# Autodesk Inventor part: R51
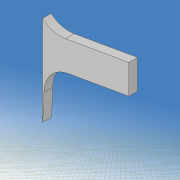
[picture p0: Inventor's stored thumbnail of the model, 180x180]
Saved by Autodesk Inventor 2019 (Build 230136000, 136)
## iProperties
Created: 2021-05
Part Number: R51
Material: 一般
Document SubType Name: Modeling
Designer: kikut
Density: 1 g/cm^3
Appearance: 既定
Mass: 0.00804985 g
Surface Area: 0.369476 cm^2
Volume: 0.00804985 cm^3
Author: kikut
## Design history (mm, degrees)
sketch "スケッチ1"
  geometry: L1 (80, 60)-(-80, 60); L2 (-80, 60)-(-80, -60); L3 (-80, -60)-(80, -60); L4 (80, -60)-(80, 60); L5 (80, 60)-(-80, -60); L6 (-80, 60)-(80, -60); 1 further point
  constraints: 12 end point, 2 midpoint, 2 parallel, 1 horizontal, 1 perpendicular
  dimensions: "d0" = 160 distance of L2.end L3.end; "d1" = 120 distance of L1.end L2.end
extrude "押し出し1" new body sketch "スケッチ1" stored distance "d2" = 0.6; taper "d3" = 0 deg
sketch "スケッチ2"
  geometry: L1 (-140, 0)-(140, 0) reference; L2 (0, -54)-(20, -30); L3 (0, 54)-(20, 30); L4 (0, -3)-(6.514, -3); L5 (6.514, -3)-(16, -6); L6 (16, -6)-(24, -3); L7 (24, -3)-(33.716, -3); L8 (0, 3)-(6.514, 3); L9 (6.514, 3)-(16, 6); L10 (16, 6)-(24, 3); L11 (24, 3)-(33.716, 3); L12 (0, -98)-(0, 98) reference; L13 (-100, -70)-(100, -70); L14 (100, -70)-(100, 70); L15 (100, 70)-(-100, 70); L16 (-100, 70)-(-100, -70); L17 (-100, -70)-(100, 70); L18 (100, -70)-(-100, 70); A1 r 60 centre (54.312, 28.5) between (0, 54) and (0, 3); A2 r 60 centre (54.312, -28.5) between (0, -3) and (0, -54); A3 r 18.111 centre (18, -12) between (20, -30) and (33.716, -3); A4 r 18.111 centre (18, 12) between (33.716, 3) and (20, 30); 1 further point
  constraints: 32 end point, 8 point on circle, 8 symmetric about line, 4 centre point, 3 horizontal, 2 collinear, 2 midpoint, 2 parallel, 1 perpendicular
  dimensions: "d5" = 60 radius of A1; "d6" = 6 distance of L8.start L4.start; "d7" = 108 distance of L3.start L2.start; "d8" = 0 horizontal distance of L3.start L8.start; "d9" = 60 distance of L3.end L2.end; "d10" = 0 horizontal distance of point (0, 0) L3.start; "d11" = 20 horizontal distance of L3.start L3.end; "d12" = 24 distance of A4.centre A3.centre; "d13" = 6 distance of L11.end L7.end; "d14" = 12 distance of L9.end L5.end; "d15" = 16 distance from line of L12 L5.end; "d16" = 24 distance from line of L6.end L12; "d17" = 200 distance of L14.end L15.end; "d18" = 140 distance of L15.end L13.start; "d30" = 18 distance from line of L12 A4.centre
extrude "押し出し2" cut sketch "スケッチ2" stored distance "d19" = 10; taper "d20" = 0 deg
sketch "スケッチ3"
  geometry: L1 (49.705, -17.97)-(33.948, -15.191); L2 (33.948, -15.191)-(34.295, -13.222); L3 (34.295, -13.222)-(50.052, -16); L4 (50.052, -16)-(49.705, -17.97); L5 (49.705, -17.97)-(34.295, -13.222); L6 (33.948, -15.191)-(50.052, -16); L7 (50.052, 16)-(34.295, 13.222); L8 (34.295, 13.222)-(33.948, 15.191); L9 (33.948, 15.191)-(49.705, 17.97); L10 (49.705, 17.97)-(50.052, 16); L11 (50.052, 16)-(33.948, 15.191); L12 (34.295, 13.222)-(49.705, 17.97); L13 (-112, 0)-(112, 0) reference; L14 (0, -84)-(0, 84) reference; 3 further points
  constraints: 24 end point, 4 midpoint, 4 parallel, 2 perpendicular, 2 symmetric about line
  dimensions: "d21" = 2 distance of L3.end L1.start; "d22" = 2 distance of L9.end L7.start; "d23" = 16 distance of L8.end L9.end; "d24" = 42 distance from line of L14 point (42, 15.596); "d26" = 10 deg angle of L7 L13; "d62" = 16 distance from line of L3.end L13
extrude "押し出し3" join sketch "スケッチ3" distance "d27" = 0.6; taper "d28" = 0 deg
fillet "フィレット1" dims "d31" = 2
fillet "フィレット2" dims "d32" = 1
sketch "スケッチ6"
  geometry: L1 (-20, 60)-(80, 60); L2 (80, 60)-(80, -60); L3 (80, -60)-(-20, -60); L4 (-20, -60)-(-20, 60); L5 (-46.168, 0)-(93.832, 0) reference; L6 (0, -84)-(0, 84) reference; L7 (36, 10)-(42, 10); L8 (42, 10)-(42, 20); L9 (42, 20)-(36, 20); L10 (36, 20)-(36, 10); 1 further point
  constraints: 16 end point, 4 parallel, 2 horizontal, 2 perpendicular, 1 other
  dimensions: "d63" = 120 distance of L3.end L1.start; "d64" = 100 distance of L1.start L1.end; "d65" = 20 distance between parallel lines of L6 L4; "d66" = 6 distance of L8.end L9.end; "d73" = 10 distance of L9.end L7.start; "d74" = 10 distance between parallel lines of L7 L5; "d75" = 56 distance between parallel lines of L10 L4
extrude "押し出し4" cut sketch "スケッチ6" stored distance "d70" = 10; taper "d71" = 0 deg
node "ソリッド1"
